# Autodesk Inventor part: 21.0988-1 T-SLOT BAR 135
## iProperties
Created: 2006-12
Part Number: 21.0988-1 T-SLOT BAR 135
Material: Steel
Document SubType Name: Modeling
Designer: Andy Moles
Author: Andy Moles
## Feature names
1. Extrusion1
2. Hole1
